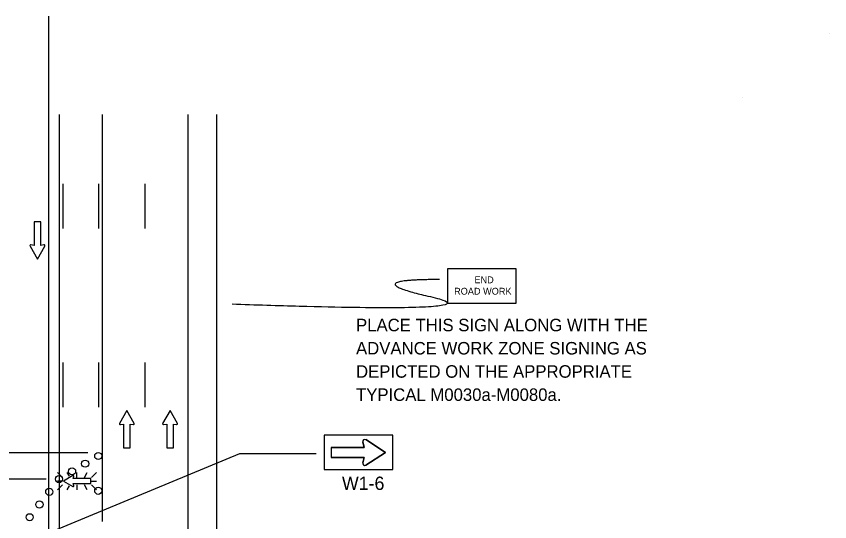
# Model space of a CAD drawing. Extents: x 16399 to 18476, y 7023 to 8321.
# Drawn here: x 17017.1 to 17472.5, y 7979.3 to 8262.3 of the extents above; entities that cross this region are included whole.
import ezdxf

# ---------------------------------------------------------------- set-up
doc = ezdxf.new("R2010")
doc.units = 0
for name, color, linetype in [('ALI_LEGAL_EX', 7, 'Continuous'), ('BORDER', 7, 'Continuous'), ('MT_SCRATCH_LEVEL_E', 7, 'Continuous'), ('PAVT_EDGE_EX', 7, 'Continuous'), ('TRAFFIC_SIGNS_PR', 7, 'Continuous'), ('TYPICAL_TEXT_DIMEN_PR', 7, 'Continuous')]:
    doc.layers.add(name, color=color, linetype=linetype)

msp = doc.modelspace()

# ---------------------------------------------------------------- linework, layer by layer
at = {"layer": 'ALI_LEGAL_EX'}
for points in [[(17043.08, 8168.47), (17043.08, 8143.47)], [(17063.08, 8168.47), (17063.08, 8143.47)], [(17089.08, 8168.47), (17089.08, 8143.47)], [(17043.08, 8068.47), (17043.08, 8043.47)], [(17063.08, 8068.47), (17063.08, 8043.47)], [(17089.08, 8068.47), (17089.08, 8043.47)]]:
    msp.add_lwpolyline(points, dxfattribs=at)
at = {"layer": 'BORDER'}
for p, q in [((17472.45, 8252.73), (17472.45, 8252.73)), ((17423.55, 8217.05), (17423.55, 8217.05))]:
    msp.add_line(p, q, dxfattribs=at)
at = {"layer": 'MT_SCRATCH_LEVEL_E'}
for p, q in [((17030.82, 8147.27), (17027.08, 8147.27)), ((17027.08, 8147.27), (17027.08, 8134.01)), ((17030.82, 8147.27), (17027.08, 8147.27)), ((17027.08, 8147.27), (17027.08, 8134.01)), ((17030.82, 8134.01), (17030.82, 8147.27)), ((17030.82, 8134.01), (17030.82, 8147.27)), ((17024.82, 8133.64), (17028.97, 8126.4)), ((17024.82, 8133.64), (17028.97, 8126.4)), ((17027.08, 8134.01), (17025.3, 8134.32)), ((17027.08, 8134.01), (17025.3, 8134.32)), ((17028.97, 8126.4), (17033.08, 8133.64)), ((17028.97, 8126.4), (17033.08, 8133.64)), ((17032.6, 8134.32), (17030.82, 8134.01)), ((17032.6, 8134.32), (17030.82, 8134.01)), ((17078.97, 8041.59), (17074.86, 8034.35)), ((17078.97, 8041.59), (17074.86, 8034.35)), ((17083.12, 8034.35), (17078.97, 8041.59)), ((17083.12, 8034.35), (17078.97, 8041.59)), ((17103.15, 8041.59), (17099.03, 8034.35)), ((17103.15, 8041.59), (17099.03, 8034.35)), ((17107.29, 8034.35), (17103.15, 8041.59)), ((17107.29, 8034.35), (17103.15, 8041.59)), ((17075.35, 8033.67), (17077.12, 8033.99)), ((17075.35, 8033.67), (17077.12, 8033.99)), ((17077.12, 8033.99), (17077.12, 8020.73)), ((17077.12, 8033.99), (17077.12, 8020.73)), ((17080.87, 8020.73), (17080.87, 8033.99)), ((17080.87, 8033.99), (17082.64, 8033.67)), ((17080.87, 8020.73), (17080.87, 8033.99)), ((17080.87, 8033.99), (17082.64, 8033.67)), ((17099.52, 8033.67), (17101.29, 8033.99)), ((17099.52, 8033.67), (17101.29, 8033.99)), ((17101.29, 8033.99), (17101.29, 8020.73)), ((17101.29, 8033.99), (17101.29, 8020.73)), ((17105.03, 8020.73), (17105.03, 8033.99)), ((17105.03, 8033.99), (17106.81, 8033.67)), ((17105.03, 8020.73), (17105.03, 8033.99)), ((17105.03, 8033.99), (17106.81, 8033.67)), ((17077.12, 8020.73), (17080.87, 8020.73)), ((17077.12, 8020.73), (17080.87, 8020.73)), ((17101.29, 8020.73), (17105.03, 8020.73)), ((17101.29, 8020.73), (17105.03, 8020.73))]:
    msp.add_line(p, q, dxfattribs=at)
for centre, start, end in [((17025.23, 8133.86), 80.0362, 209.7731), ((17025.23, 8133.86), 80.0362, 209.7731), ((17032.67, 8133.86), 330.4248, 99.9638), ((17032.67, 8133.86), 330.4248, 99.9638), ((17075.27, 8034.13), 150.4248, 279.9638), ((17075.27, 8034.13), 150.4248, 279.9638), ((17082.71, 8034.13), 260.0362, 29.7731), ((17082.71, 8034.13), 260.0362, 29.7731), ((17099.44, 8034.13), 150.4248, 279.9638), ((17099.44, 8034.13), 150.4248, 279.9638), ((17106.88, 8034.13), 260.0362, 29.7731), ((17106.88, 8034.13), 260.0362, 29.7731)]:
    msp.add_arc(centre, 0.463, start, end, dxfattribs=at)
at = {"layer": 'PAVT_EDGE_EX'}
for p, q in [((17035.15, 8262.34), (17035.15, 7433.15)), ((17041.08, 8207.29), (17041.08, 7950.98)), ((17065.08, 8207.29), (17065.08, 7979.43)), ((17113.08, 8207.29), (17113.08, 7352.54)), ((17129.08, 8207.29), (17129.08, 7352.54))]:
    msp.add_line(p, q, dxfattribs=at)
at = {"layer": 'TRAFFIC_SIGNS_PR'}
for p, q in [((17211.85, 8020.93), (17211.01, 8023.99)), ((17212.69, 8025.23), (17223.85, 8018.13)), ((17193.45, 8020.93), (17211.85, 8020.93)), ((17193.45, 8020.93), (17193.45, 8015.33)), ((17211.85, 8015.33), (17193.45, 8015.33)), ((17211.01, 8012.27), (17211.85, 8015.33)), ((17223.85, 8018.13), (17212.69, 8011.03)), ((17040.17, 8006.9), (17042.98, 8004.08)), ((17046.89, 8004.72), (17045.62, 8006.9)), ((17051.07, 8004.08), (17051.07, 8006.9)), ((17055.2, 8004.08), (17056.83, 8006.9)), ((17059.15, 8004.08), (17061.97, 8006.9)), ((17042.98, 8002.05), (17040.17, 8002.05)), ((17059.15, 8002.05), (17061.97, 8002.05)), ((17040.17, 7997.2), (17042.98, 8000.02)), ((17045.6, 7997.2), (17046.81, 7999.29)), ((17051.07, 8000.02), (17051.07, 7997.2)), ((17056.86, 7997.2), (17055.23, 8000.02)), ((17059.15, 8000.02), (17061.97, 7997.2))]:
    msp.add_line(p, q, dxfattribs=at)
for points in [[(17258.56, 8101.69), (17296.96, 8101.69), (17296.96, 8120.89), (17258.56, 8120.89)], [(17189.45, 8008.53), (17227.85, 8008.53), (17227.85, 8027.73), (17189.45, 8027.73)]]:
    msp.add_lwpolyline(points, close=True, dxfattribs=at)
for points in [[(17211.01, 8023.99), (17211.85, 8020.93), (17193.45, 8020.93), (17193.45, 8015.33), (17211.85, 8015.33), (17211.01, 8012.27)], [(17212.69, 8011.03), (17223.85, 8018.13), (17212.69, 8025.23)], [(17048.74, 8005.07), (17043.43, 8002.05), (17048.74, 7999.01)], [(17049.24, 7999.37), (17049.01, 8000.67), (17058.74, 8000.67), (17058.74, 8003.41), (17049.01, 8003.41), (17049.24, 8004.71)]]:
    msp.add_lwpolyline(points, dxfattribs=at)
for centre in [(17062.97, 8016.09), (17055.64, 8011.78), (17048.31, 8007.48), (17040.98, 8003.17), (17035.56, 7996.04), (17062.97, 7996.6), (17030.07, 7988.91), (17024.58, 7981.78)]:
    msp.add_circle(centre, 2, dxfattribs=at)
for centre, radius, start, end in [((17212.09, 8024.28), 1.12, 57.5304, 195.3269), ((17212.09, 8024.28), 1.12, 57.5304, 195.3269), ((17212.09, 8011.97), 1.12, 164.6731, 302.4696), ((17212.09, 8011.97), 1.12, 164.6731, 302.4696), ((17048.91, 8004.77), 0.341, 350.7308, 118.8916), ((17048.91, 7999.31), 0.341, 241.4833, 9.9593)]:
    msp.add_arc(centre, radius, start, end, dxfattribs=at)
msp.add_open_spline([(17253.97, 8114.89), (17206.74, 8114.89), (17291.76, 8095.55), (17137.93, 8101.04)], degree=2, dxfattribs=at)
at = {"layer": 'TYPICAL_TEXT_DIMEN_PR'}
for p, q in [((16927.98, 8018.1), (17057.12, 8018.1)), ((17028.06, 7970.11), (17142.3, 8017.42)), ((17142.3, 8017.42), (17184.97, 8017.42)), ((17033.9, 8003.17), (16892.89, 8003.17)), ((17033.9, 8003.17), (16902.4, 8003.17))]:
    msp.add_line(p, q, dxfattribs=at)

# ---------------------------------------------------------------- texts
at = {"layer": 'TRAFFIC_SIGNS_PR'}
for s, height, p in [('END', 3.831, (17273.56, 8112.82)), ('ROAD WORK', 3.831, (17262.17, 8106.44)), ('PLACE THIS SIGN ALONG WITH THE', 7, (17207.28, 8085.92)), ('ADVANCE WORK ZONE SIGNING AS', 7, (17207.28, 8072.92)), ('DEPICTED ON THE APPROPRIATE', 7, (17207.28, 8059.92)), ('TYPICAL M0030a-M0080a.', 7, (17207.28, 8046.92)), ('W1-6', 7.44, (17199.39, 7997.09))]:
    msp.add_text(s, height=height, dxfattribs=at).set_placement(p)

doc.saveas('drawing.dxf')
